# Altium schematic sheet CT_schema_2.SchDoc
size 461 x 227 mm
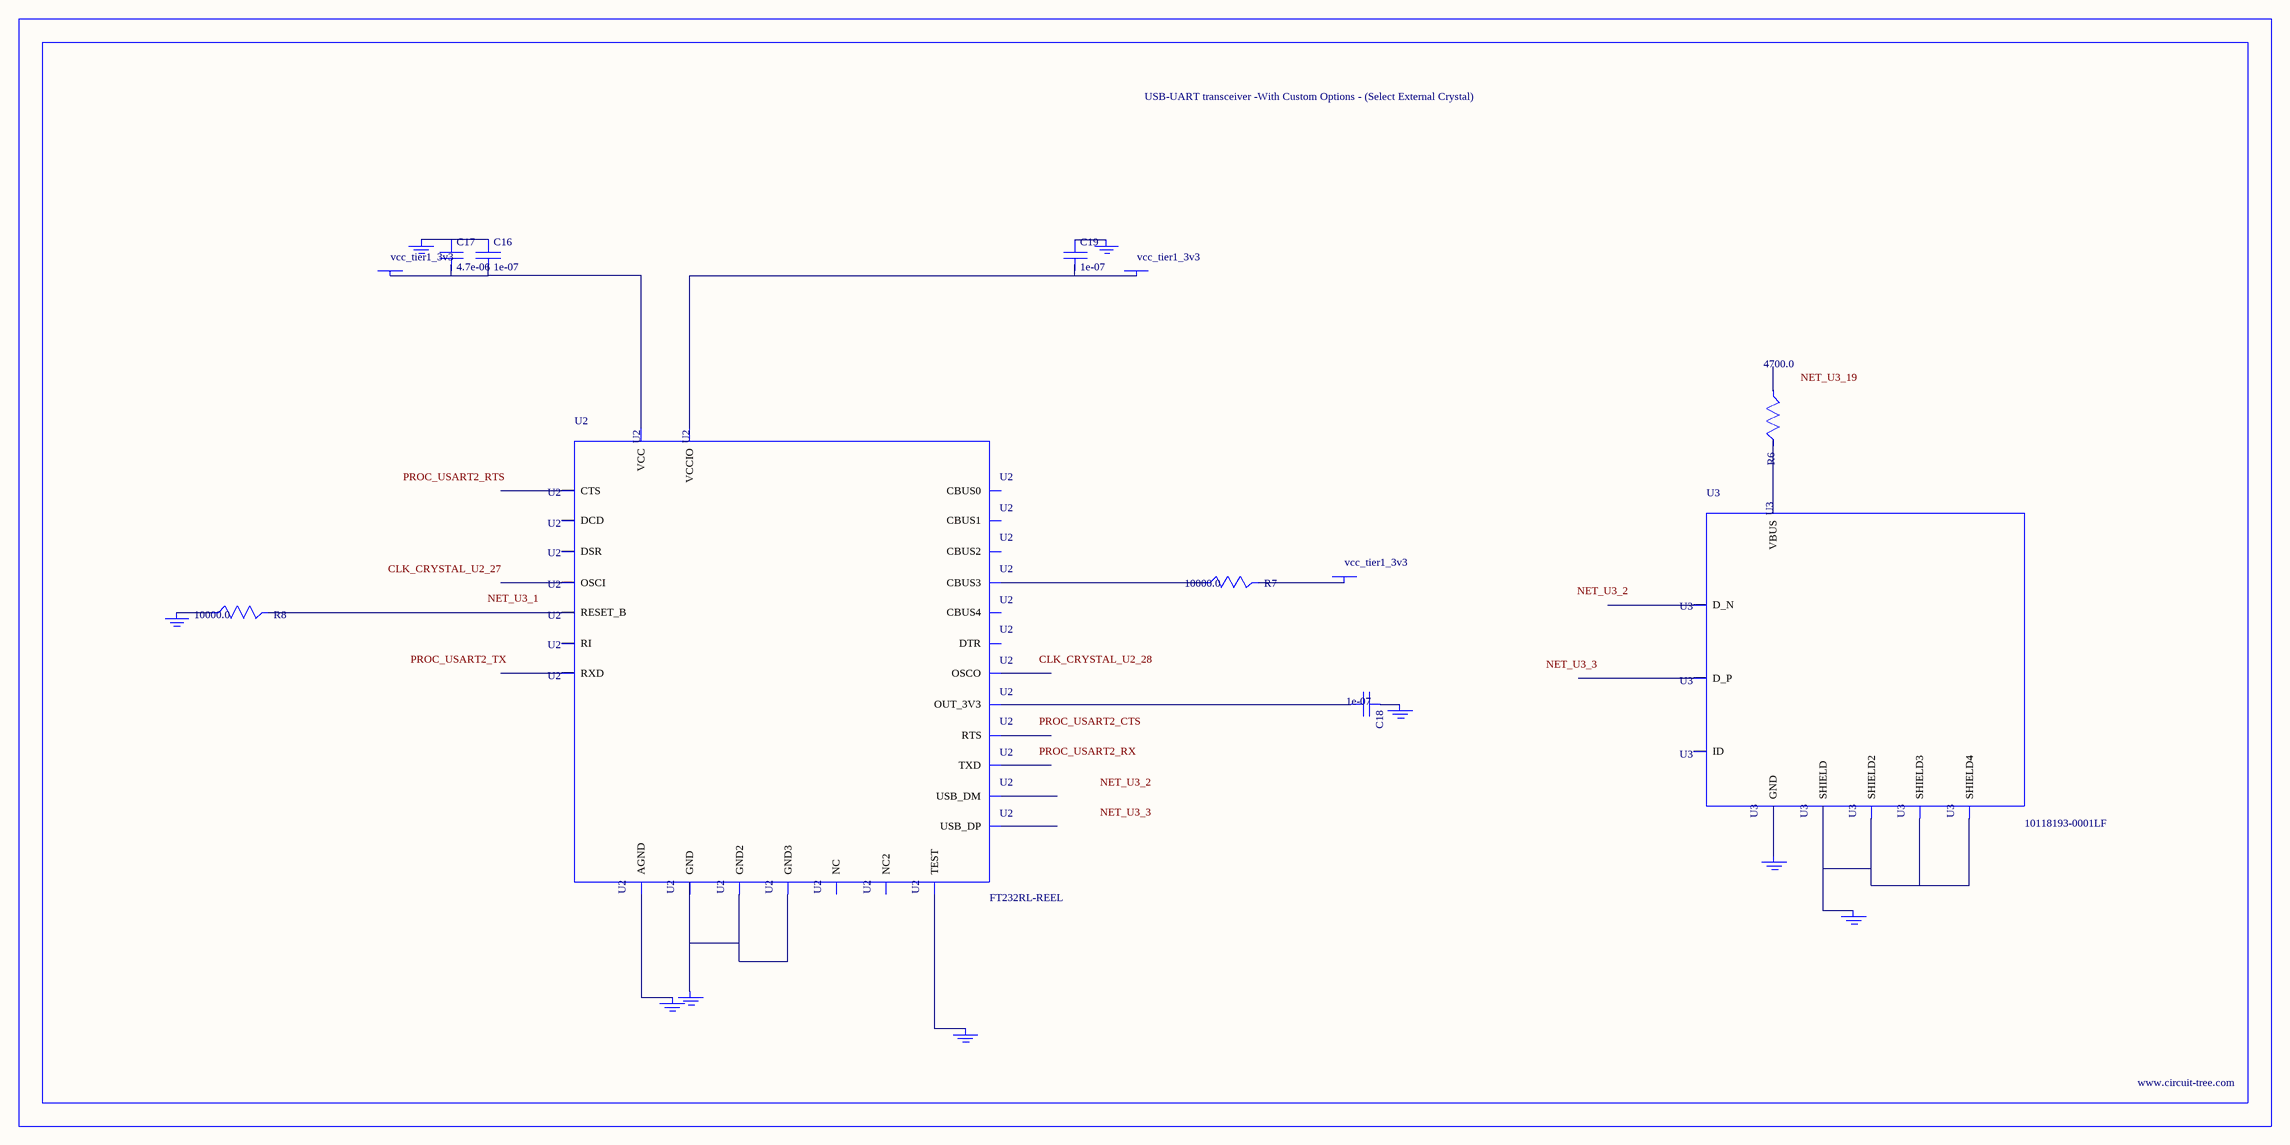
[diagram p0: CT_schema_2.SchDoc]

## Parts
BORDER1  (no value)
C16  1e-07  [C0402]
C17  4.7e-06  [C0805]
C18  1e-07  [C0402]
C19  1e-07  [C0402]
GND_INSTANCE_1_0  (no value)
GND_INSTANCE_1_1  (no value)
GND_INSTANCE_1_2  (no value)
GND_INSTANCE_1_3  (no value)
GND_INSTANCE_1_4  (no value)
GND_INSTANCE_1_5  (no value)
GND_INSTANCE_1_6  (no value)
GND_INSTANCE_1_7  (no value)
GND_INSTANCE_1_8  (no value)
POWER_INSTANCE_1_0  vcc_tier1_3v3
POWER_INSTANCE_1_1  vcc_tier1_3v3
POWER_INSTANCE_1_2  vcc_tier1_3v3
R6  4700.0  [R0603]
R7  10000.0  [R0603]
R8  10000.0  [R0603]
U2  FT232RL-REEL  [SSOP-28]
U3  10118193-0001LF  [FCI_10118193-0001LF]

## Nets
NetC16_1: C16.1 C17.1 GND_INSTANCE_1_3.0(GND)
NetC16_2: C16.2 C17.2 POWER_INSTANCE_1_2.0(PWR) U2.20(VCC)
NetC18_1: C18.1 GND_INSTANCE_1_1.0(GND)
NetC18_2: C18.2 U2.17(OUT_3V3)
NetC19_1: C19.1 GND_INSTANCE_1_0.0(GND)
NetC19_2: C19.2 POWER_INSTANCE_1_0.0(PWR) U2.4(VCCIO)
NetGND_INSTANCE_1_2_0: GND_INSTANCE_1_2.0(GND) R8.1
NetGND_INSTANCE_1_4_0: GND_INSTANCE_1_4.0(GND) U2.25(AGND)
NetGND_INSTANCE_1_5_0: GND_INSTANCE_1_5.0(GND) U2.26(TEST)
NetGND_INSTANCE_1_6_0: GND_INSTANCE_1_6.0(GND) U2.7(GND) U2.18(GND2) U2.21(GND3)
NetGND_INSTANCE_1_7_0: GND_INSTANCE_1_7.0(GND) U3.6(SHIELD) U3.7(SHIELD2) U3.8(SHIELD3) U3.9(SHIELD4)
NetGND_INSTANCE_1_8_0: GND_INSTANCE_1_8.0(GND) U3.5(GND)
NetPOWER_INSTANCE_1_1_0: POWER_INSTANCE_1_1.0(PWR) R7.2
NetR6_2: R6.2 U3.1(VBUS)
NetR7_1: R7.1 U2.14(CBUS3)
NetR8_2: R8.2 U2.19(RESET_B)

Not connected (* = marked no-connect by the designer): R6 1; U2 1(TXD) 2(DTR) 3(RTS) 5(RXD) 6(RI) 8(NC) 9(DSR) 10(DCD) 11(CTS) 12(CBUS4) 13(CBUS2) 15(USB_DP) 16(USB_DM) 22(CBUS1) 23(CBUS0) 24(NC2) 27(OSCI) 28(OSCO); U3 2(D_N) 3(D_P) 4(ID)

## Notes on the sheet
- Labels drawn without touching a wire or pin: CLK_CRYSTAL_U2_27, CLK_CRYSTAL_U2_28, NET_U3_1, NET_U3_2, NET_U3_3, NET_U3_19, PROC_USART2_CTS, PROC_USART2_RTS, PROC_USART2_RX, PROC_USART2_TX

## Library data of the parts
BORDER1 = BORDER_PAGE1
C16 C18 C19 = C0402C104K3RACTU
C17 = C0805C475K4RACTU
GND_INSTANCE_1_0-GND_INSTANCE_1_8 = GND
POWER_INSTANCE_1_0-POWER_INSTANCE_1_2 = PWR
R6 = RC0603JR-074K7L
R7 R8 = RC0603JR-0710KL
